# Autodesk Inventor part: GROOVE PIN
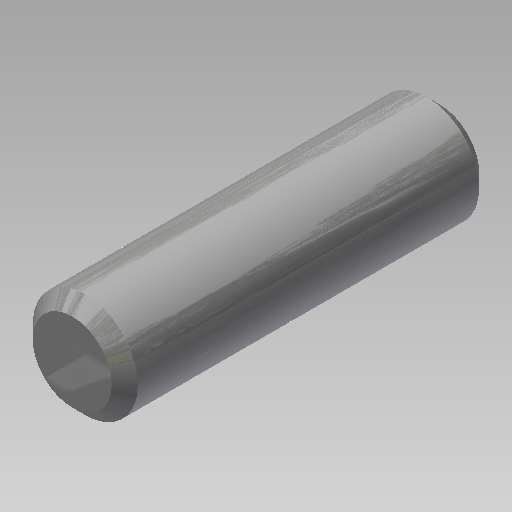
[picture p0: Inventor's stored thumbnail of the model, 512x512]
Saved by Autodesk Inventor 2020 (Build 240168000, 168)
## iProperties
Part Number: GROOVE PIN
Document SubType Name: Modeling
Created: 2003-11
Designer: Autodesk, Inc.
Manufacturer: Standard
Standards Organization: Custom
Mass: 5.43614 g
Surface Area: 4.86691 cm^2
Volume: 0.692502 cm^3
Density: 7.85 g/cm^3
Material: Steel, Mild
Appearance: Steel
Control State: 0
Master: False
Checked Out: False
Shininess: 64.0
Length Units: 11272
Angle Units: 11279
Time Units: 11290
Mass Units: 11286
Length Display Precision: 3
Angle Display Precision: 2
Compacted: True
Density: 0.0
Volumn: 0.0
Area: 0.0
PropertySet Name: Model Information
Author: Autodesk, Inc.
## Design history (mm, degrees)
sketch "Sketch1"
  geometry: C1 r 3.175 at (0, 0); 1 further point
  constraints: 1 centre point, 1 coincident
  dimensions: "d0" = 6.35 diameter of C1
extrude "Extrusion1" new body sketch "Sketch1" distance "d1" = 22.225; taper "d2" = 0 deg
chamfer "Chamfer1" distance "d3" = 0.7874; stored, may be unused: second distance "d4" = 3.175, angle "d5" = 45 deg
body "Solid1"
